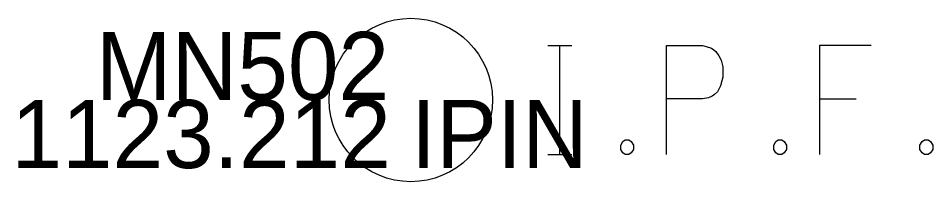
# Model space of a CAD drawing. Extents: x 2402028 to 2407435, y 498611 to 499105.
# Drawn here: x 2404191.61 to 2404205.05, y 499102.41 to 499104.81 of the extents above; entities that cross this region are included whole.
import ezdxf

# ---------------------------------------------------------------- set-up
doc = ezdxf.new("R2010")
doc.units = 0
for name, color, linetype in [('_CIVIL_CONSTRUCTION', 7, 'Continuous'), ('RW_X_CL_100_Bearings', 7, 'Continuous'), ('RW_X_CL_100_Cardinal_Points', 7, 'Continuous'), ('RW_X_CL_100_Stations', 7, 'Continuous')]:
    doc.layers.add(name, color=color, linetype=linetype)

msp = doc.modelspace()

# ---------------------------------------------------------------- linework, layer by layer
at = {"layer": 'RW_X_CL_100_Stations'}
for points in [[(2404199.394, 499104.411), (2404199.747, 499104.411)], [(2404199.57, 499102.811), (2404199.57, 499104.411)], [(2404201.135, 499102.811), (2404201.135, 499104.411), (2404201.665, 499104.411), (2404201.72, 499104.398), (2404201.797, 499104.373), (2404201.83, 499104.348), (2404201.863, 499104.322), (2404201.907, 499104.259), (2404201.94, 499104.196), (2404201.962, 499104.096), (2404201.962, 499103.944), (2404201.951, 499103.894), (2404201.929, 499103.818), (2404201.885, 499103.73), (2404201.841, 499103.692), (2404201.808, 499103.667), (2404201.753, 499103.642), (2404201.665, 499103.63), (2404201.135, 499103.63)], [(2404204.145, 499104.411), (2404203.384, 499104.411), (2404203.384, 499102.811)], [(2404203.384, 499103.63), (2404203.924, 499103.63)], [(2404200.529, 499103.025), (2404200.584, 499103.025), (2404200.617, 499103), (2404200.65, 499102.949), (2404200.65, 499102.886), (2404200.617, 499102.836), (2404200.584, 499102.811), (2404200.529, 499102.811), (2404200.496, 499102.836), (2404200.463, 499102.886), (2404200.463, 499102.949), (2404200.496, 499103), (2404200.529, 499103.025)], [(2404202.778, 499103.025), (2404202.833, 499103.025), (2404202.866, 499103), (2404202.899, 499102.949), (2404202.899, 499102.886), (2404202.866, 499102.836), (2404202.833, 499102.811), (2404202.778, 499102.811), (2404202.745, 499102.836), (2404202.712, 499102.886), (2404202.712, 499102.949), (2404202.745, 499103), (2404202.778, 499103.025)], [(2404204.927, 499103.025), (2404204.982, 499103.025), (2404205.015, 499103), (2404205.048, 499102.949), (2404205.048, 499102.886), (2404205.015, 499102.836), (2404204.982, 499102.811), (2404204.927, 499102.811), (2404204.894, 499102.836), (2404204.861, 499102.886), (2404204.861, 499102.949), (2404204.894, 499103), (2404204.927, 499103.025)], [(2404199.394, 499102.811), (2404199.747, 499102.811)]]:
    msp.add_lwpolyline(points, dxfattribs=at)
msp.add_circle((2404197.379, 499103.611), 1.2, dxfattribs=at)

# ---------------------------------------------------------------- texts
at = {"layer": '_CIVIL_CONSTRUCTION'}
msp.add_text('MN502', height=1, dxfattribs=at).set_placement((2404192.749, 499103.611))
at = {"layer": 'RW_X_CL_100_Bearings'}
msp.add_text('1123.212', height=1, dxfattribs=at).set_placement((2404191.508, 499102.611))
at = {"layer": 'RW_X_CL_100_Cardinal_Points'}
msp.add_text('IPIN', height=1, dxfattribs=at).set_placement((2404197.379, 499102.611))

doc.saveas('drawing.dxf')
